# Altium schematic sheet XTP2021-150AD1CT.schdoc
size 127 x 101 mm
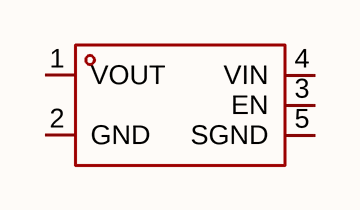
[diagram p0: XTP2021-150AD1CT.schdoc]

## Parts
U?  xtp2021-150ad1ct  [UDFN-4_L1.0-W1.0-P0.65-TL]  (value not drawn)

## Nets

Not connected (* = marked no-connect by the designer): U? 1(VOUT) 2(GND) 3(EN) 4(VIN) 5(SGND)

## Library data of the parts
U? = xtp2021-150ad1ct: 输出极性:正极;工作电压:5.5V;输出电压:1.5V;输出电流:300mA;电源纹波抑制比(PSRR):75dB@(1kHz);输出类型:固定;; Manufacturer: XTX(芯天下); AddInBom: yes; ModelId: 9c2eebc267f642aab45e7193d1ab7813; ModelTransform: 40.1574,39.37394,0,0,0,0,0,0,0; Output Configuration: 正极; Voltage - Supply: 5.5V; Output Voltage: 1.5V; Output Current: 300mA; Voltage Dropout: 180mV@(300mA); standby current: 1uA; Noise: 67uVrms; Output Type: 固定; Number of Outputs: 1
